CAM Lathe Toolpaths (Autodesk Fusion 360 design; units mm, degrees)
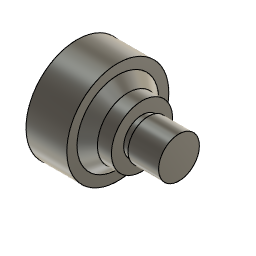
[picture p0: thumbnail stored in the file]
sketch "Sketch1" plane through (0, 0, 0) normal (0, 1, 0) x axis (1, 0, 0)
  line L1 (63.5, 0) -> (0, 0)
  line L2 (38.1, 0) -> (0, 0)
  line L3 (38.1, -6.35) -> (38.1, 0)
  line L4 (60.325, -6.35) -> (38.1, -6.35)
  line L5 (63.5, -9.525) -> (60.325, -6.35)
  line L6 (63.5, -12.7) -> (63.5, -9.525)
  line L7 (44.45, -12.7) -> (63.5, -12.7)
  line L8 (44.45, -11.43) -> (44.45, -12.7)
  line L9 (40.4812, -11.43) -> (44.45, -11.43)
  line L10 (40.4812, -19.05) -> (40.4812, -11.43)
  line L11 (31.75, -19.05) -> (40.4812, -19.05)
  line L12 (25.4, -25.4) -> (31.75, -19.05)
  line L13 (25.4, -31.75) -> (25.4, -25.4)
  line L14 (0, -31.75) -> (25.4, -31.75)
  line L15 (0, 0) -> (0, -31.75)
  line L16 (63.5, 0) -> (63.5, -9.525)
  point P1 (0, 0)
  point P2 (0, 0)
  point P4 (0, 0)
  point P5 (38.1, 0)
  point P18 (0, 0)
  point P3 (63.5, 0)
  point P7 (60.325, -6.35)
  point P8 (63.5, -9.525)
  point P10 (44.45, -12.7)
  point P11 (44.45, -11.43)
  point P9 (63.5, -12.7)
  point P14 (31.75, -19.05)
  point P15 (25.4, -25.4)
  point P16 (25.4, -31.75)
  point P17 (0, -31.75)
  coincident P1 P2
  horizontal L1
  coincident P1 P4
  coincident L1 P5
  parallel L1 L2
  perpendicular L2 L3
  perpendicular L3 L4
  perpendicular L4 L6
  perpendicular L6 L7
  perpendicular L7 L8
  perpendicular L8 L9
  perpendicular L9 L10
  perpendicular L10 L11
  perpendicular L11 L13
  perpendicular L13 L14
  coincident P1 P18
  perpendicular L1 L15
  coincident P3 L6
  dimension "d1" distance P2 P3 = 63.5
  dimension "d2" angle L4 L5 = 45
  dimension "d3" distance P7 P8 = 3.175
  dimension "d4" = 12.7
  dimension "d5" distance L3 L6 = 25.4
  dimension "d7" distance L8 L10 = 3.9688
  dimension "d8" distance P10 P11 = 1.27
  dimension "d9" distance P9 P10 = 19.05
  dimension "d10" angle L11 L12 = 45
  dimension "d11" distance P14 P15 = 6.35
  dimension "d12" = 63.5
  dimension "d13" distance P16 P17 = 25.4
  dimension "d15" = 25.4
  dimension "d16" = 38.1
revolve "Revolve1" sketch "Sketch1" AlongAngle 360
